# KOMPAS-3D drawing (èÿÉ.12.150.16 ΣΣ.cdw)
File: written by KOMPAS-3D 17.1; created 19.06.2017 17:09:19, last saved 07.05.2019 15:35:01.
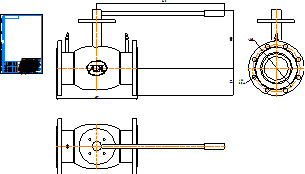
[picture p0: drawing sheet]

Sheet 1: A4, portrait

Title block, sheet 1: name: КШР.12.150.16 фф; material: Внимание! Данный продукт является объектом авторского права ООО «Торговый Дом АДЛ». / Запрещается изменение, копирование, распространение / (в том числе путем копирования на другие сайты и ресурсы в Интернете) / или любое иное использование информации и объектов без предварительного / согласия правообладателя (ООО «Торговый Дом АДЛ»).; scale: 1:1; sheets: 1; organisation: ООО "Торговый дом АДЛ"; sheet format: A4; stored path: C:\Users\tra\Desktop\2д чертежи\Шаровые краны БИВАЛ\КШР_Бивал_серия_12\KOMPAS 2D\КШР.12.150.16 фф.cdw

Views: Спереди 1, Проекционный вид 2, Проекционный вид 3
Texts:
  Klimkovich
  ADL
Dimensions and other numbers on the sheet: 407; 645; 291,6; 140; 240; 22; 8 Отв.; 1:1; 1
